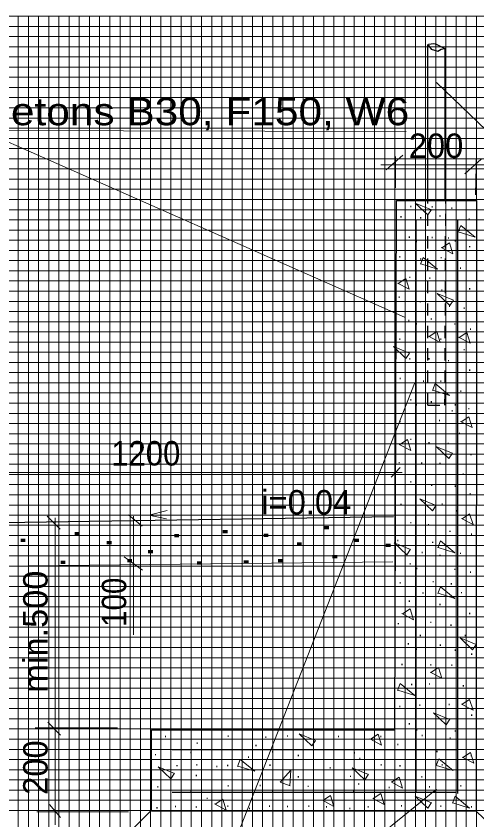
# Model space of a CAD drawing. Extents: x -265.4 to -236, y -5.8 to 40.6.
# Drawn here: x -244.84 to -240.31, y 7.22 to 15.11 of the extents above; entities that cross this region are included whole.
import ezdxf
from ezdxf.enums import TextEntityAlignment as Align

# ---------------------------------------------------------------- set-up
doc = ezdxf.new("R2010")
doc.units = 0
doc.header["$LTSCALE"] = 0.04
doc.linetypes.add('MEDIUM_DASHED', pattern=[4.5, 3, -1.5])
for name, color, linetype, lineweight in [('1', 7, 'Continuous', 13), ('2', 7, 'MEDIUM_DASHED', 13), ('3', 7, 'Continuous', 13), ('4', 7, 'Continuous', 35), ('63', 7, 'Continuous', 13)]:
    doc.layers.add(name, color=color, linetype=linetype, lineweight=lineweight)

msp = doc.modelspace()

# ---------------------------------------------------------------- linework, layer by layer
at = {"layer": '1'}
for p, q in [((-244.816, 15.11), (-244.816, -5.836)), ((-244.716, 15.11), (-244.716, -5.836)), ((-244.516, 15.11), (-244.516, -5.836)), ((-244.416, 15.11), (-244.416, -5.836)), ((-244.316, 15.11), (-244.316, -5.836)), ((-244.216, 15.11), (-244.216, -5.836)), ((-244.016, 15.11), (-244.016, -5.836)), ((-243.916, 15.11), (-243.916, -5.836)), ((-243.816, 15.11), (-243.816, -5.836)), ((-243.716, 15.11), (-243.716, -5.836)), ((-243.516, 15.11), (-243.516, -5.836)), ((-243.416, 15.11), (-243.416, -5.836)), ((-243.316, 15.11), (-243.316, -5.836)), ((-243.216, 15.11), (-243.216, -5.836)), ((-243.016, 15.11), (-243.016, -5.836)), ((-242.916, 15.11), (-242.916, -5.836)), ((-242.816, 15.11), (-242.816, -5.836)), ((-242.716, 15.11), (-242.716, -5.836)), ((-242.516, 15.11), (-242.516, -5.836)), ((-242.416, 15.11), (-242.416, -5.836)), ((-242.316, 15.11), (-242.316, -5.836)), ((-242.216, 15.11), (-242.216, -5.836)), ((-242.016, 15.11), (-242.016, -5.836)), ((-241.916, 15.11), (-241.916, -5.836)), ((-241.816, 15.11), (-241.816, -5.836)), ((-241.716, 15.11), (-241.716, -5.836)), ((-241.516, 15.11), (-241.516, -5.836)), ((-241.416, 15.11), (-241.416, -5.836)), ((-241.316, 15.11), (-241.316, -5.836)), ((-241.216, 15.11), (-241.216, -5.836)), ((-241.016, 15.11), (-241.016, -5.836)), ((-240.916, 15.11), (-240.916, -5.836)), ((-240.816, 15.11), (-240.816, -5.836)), ((-240.716, 15.11), (-240.716, -5.836)), ((-240.516, 15.11), (-240.516, -5.836)), ((-240.416, 15.11), (-240.416, -5.836)), ((-240.316, 15.11), (-240.316, -5.836)), ((-265.117, 15.009), (-236.007, 15.009)), ((-265.117, 14.909), (-236.007, 14.909)), ((-265.117, 14.809), (-236.007, 14.809)), ((-265.117, 14.709), (-236.007, 14.709)), ((-265.117, 14.509), (-236.007, 14.509)), ((-265.117, 14.409), (-236.007, 14.409)), ((-265.117, 14.309), (-236.007, 14.309)), ((-265.117, 14.209), (-236.007, 14.209)), ((-265.117, 14.009), (-236.007, 14.009)), ((-265.117, 13.909), (-236.007, 13.909)), ((-265.117, 13.809), (-236.007, 13.809)), ((-265.107, 13.708), (-235.997, 13.708)), ((-265.117, 13.509), (-236.007, 13.509)), ((-265.117, 13.409), (-236.007, 13.409)), ((-265.117, 13.309), (-236.007, 13.309)), ((-265.117, 13.209), (-236.007, 13.209)), ((-265.117, 13.009), (-236.007, 13.009)), ((-265.117, 12.909), (-236.007, 12.909)), ((-265.117, 12.809), (-236.007, 12.809)), ((-265.117, 12.709), (-236.007, 12.709)), ((-265.117, 12.509), (-236.007, 12.509)), ((-265.117, 12.409), (-236.007, 12.409)), ((-265.117, 12.309), (-236.007, 12.309)), ((-265.117, 12.209), (-236.007, 12.209)), ((-265.117, 12.009), (-236.007, 12.009)), ((-265.117, 11.909), (-236.007, 11.909)), ((-265.117, 11.809), (-236.007, 11.809)), ((-265.117, 11.709), (-236.007, 11.709)), ((-265.117, 11.509), (-236.007, 11.509)), ((-265.117, 11.409), (-236.007, 11.409)), ((-265.117, 11.309), (-236.007, 11.309)), ((-265.117, 11.209), (-236.007, 11.209)), ((-265.117, 11.009), (-236.007, 11.009)), ((-265.117, 10.909), (-236.007, 10.909)), ((-265.117, 10.809), (-236.007, 10.809)), ((-265.117, 10.709), (-236.007, 10.709)), ((-265.117, 10.509), (-236.007, 10.509)), ((-265.117, 10.409), (-236.007, 10.409)), ((-265.117, 10.309), (-236.007, 10.309)), ((-265.117, 10.21), (-236.007, 10.21)), ((-265.117, 10.01), (-236.007, 10.01)), ((-265.117, 9.91), (-236.007, 9.91)), ((-265.117, 9.81), (-236.007, 9.81)), ((-265.117, 9.71), (-236.007, 9.71)), ((-265.117, 9.51), (-236.007, 9.51)), ((-265.117, 9.41), (-236.007, 9.41)), ((-265.117, 9.31), (-236.007, 9.31)), ((-265.117, 9.21), (-236.007, 9.21)), ((-265.117, 9.01), (-236.007, 9.01)), ((-265.117, 8.91), (-236.007, 8.91)), ((-265.117, 8.81), (-236.007, 8.81)), ((-265.117, 8.71), (-236.007, 8.71)), ((-265.117, 8.51), (-236.007, 8.51)), ((-265.117, 8.41), (-236.007, 8.41)), ((-265.117, 8.31), (-236.007, 8.31)), ((-265.117, 8.21), (-236.007, 8.21)), ((-265.117, 8.01), (-236.007, 8.01)), ((-265.117, 7.91), (-236.007, 7.91)), ((-265.117, 7.81), (-236.007, 7.81)), ((-265.117, 7.71), (-236.007, 7.71)), ((-265.117, 7.51), (-236.007, 7.51)), ((-265.117, 7.41), (-236.007, 7.41)), ((-265.117, 7.31), (-236.007, 7.31))]:
    msp.add_line(p, q, dxfattribs=at)
at = {"layer": '2', "linetype": 'Continuous'}
for p, q in [((-244.616, 15.11), (-244.616, -5.836)), ((-243.616, 15.11), (-243.616, -5.836)), ((-242.616, 15.11), (-242.616, -5.836)), ((-241.616, 15.11), (-241.616, -5.836)), ((-240.616, 15.11), (-240.616, -5.836)), ((-265.117, 14.609), (-236.007, 14.609)), ((-265.117, 13.609), (-236.007, 13.609)), ((-265.117, 12.609), (-236.007, 12.609)), ((-265.117, 11.609), (-236.007, 11.609)), ((-265.117, 10.609), (-236.007, 10.609)), ((-265.117, 9.61), (-236.007, 9.61)), ((-265.117, 8.61), (-236.007, 8.61)), ((-265.117, 7.61), (-236.007, 7.61))]:
    msp.add_line(p, q, dxfattribs=at)
at = {"layer": '3'}
for p, q in [((-244.116, 15.11), (-244.116, -5.836)), ((-243.116, 15.11), (-243.116, -5.836)), ((-242.116, 15.11), (-242.116, -5.836)), ((-241.116, 15.11), (-241.116, -5.836)), ((-265.117, 14.109), (-236.007, 14.109)), ((-265.117, 13.109), (-236.007, 13.109)), ((-265.117, 12.109), (-236.007, 12.109)), ((-265.117, 11.109), (-236.007, 11.109)), ((-265.117, 9.11), (-236.007, 9.11)), ((-265.117, 8.11), (-236.007, 8.11))]:
    msp.add_line(p, q, dxfattribs=at)
at = {"layer": '4', "lineweight": 13}
for p, q in [((-265.117, 15.109), (-236.007, 15.109)), ((-265.117, 10.11), (-236.007, 10.11))]:
    msp.add_line(p, q, dxfattribs=at)
at = {"layer": '63', "lineweight": 25}
for p, q in [((-240.623, 13.308), (-240.623, 14.798)), ((-240.91, 13.105), (-240.91, 7.49)), ((-240.502, 13.105), (-240.502, 7.477)), ((-243.303, 7.91), (-240.502, 7.91)), ((-243.303, 7.49), (-240.528, 7.49))]:
    msp.add_line(p, q, dxfattribs=at)
at = {"layer": '63'}
for p, q in [((-241.04, 13.743), (-241.202, 13.6)), ((-240.324, 13.354), (-240.316, 13.775)), ((-241.112, 13.422), (-241.112, 13.731)), ((-240.269, 13.705), (-240.431, 13.562)), ((-241.254, 13.65), (-240.194, 13.65)), ((-241.064, 10.679), (-241.154, 10.583)), ((-247.197, 10.628), (-241.045, 10.628)), ((-244.531, 10.198), (-244.405, 10.072)), ((-244.453, 10.182), (-244.453, 7.17)), ((-243.731, 10.212), (-243.6, 10.1)), ((-243.682, 10.199), (-243.682, 9.033)), ((-242.637, 10.211), (-243.534, 10.211)), ((-243.775, 9.8), (-243.595, 9.669)), ((-241.136, 9.75), (-245.9, 9.7)), ((-244.525, 8.176), (-244.399, 8.05)), ((-243.842, 8.122), (-244.65, 8.122)), ((-243.318, 5.4), (-240.709, 7.52)), ((-244.507, 7.368), (-244.399, 7.242)), ((-243.734, 7.296), (-244.632, 7.296))]:
    msp.add_line(p, q, dxfattribs=at)
at = {"layer": '63', "linetype": 'MEDIUM_DASHED', "lineweight": 25}
msp.add_line((-240.795, 11.289), (-240.795, 13.289), dxfattribs=at)
at = {"layer": '63', "lineweight": 25}
for points in [[(-240.795, 13.289), (-240.792, 14.831), (-240.76, 14.785), (-240.694, 14.765), (-240.662, 14.785), (-240.629, 14.791), (-240.668, 14.811), (-240.708, 14.831), (-240.734, 14.837), (-240.786, 14.831)], [(-241.13, 10.192), (-247.095, 10.1), (-252.481, 6.504)]]:
    msp.add_lwpolyline(points, dxfattribs=at)
at = {"layer": '63'}
for points in [[(-240.707, 14.459), (-239.976, 13.753), (-236.293, 13.753)], [(-241.007, 13.976), (-245.174, 13.988), (-241.022, 12.153)], [(-240.758, 13.209), (-240.917, 13.274), (-240.794, 13.157), (-240.758, 13.211)], [(-240.495, 12.99), (-240.329, 12.94), (-240.471, 13.055), (-240.498, 12.988)], [(-240.655, 12.835), (-240.58, 12.884), (-240.547, 12.777), (-240.661, 12.837)], [(-240.863, 12.676), (-240.697, 12.626), (-240.839, 12.741), (-240.866, 12.674)], [(-241.086, 12.485), (-241.011, 12.534), (-240.978, 12.427), (-241.092, 12.487)], [(-240.542, 12.32), (-240.701, 12.385), (-240.578, 12.268), (-240.542, 12.322)], [(-240.781, 11.964), (-240.706, 12.013), (-240.673, 11.906), (-240.787, 11.966)], [(-240.485, 11.955), (-240.41, 12.004), (-240.377, 11.897), (-240.491, 11.957)], [(-240.973, 11.799), (-241.132, 11.864), (-241.009, 11.747), (-240.973, 11.801)], [(-240.923, 11.501), (-243.318, 5.4), (-236.668, 5.4)], [(-240.746, 11.436), (-240.58, 11.386), (-240.722, 11.501), (-240.749, 11.434)], [(-240.467, 11.127), (-240.392, 11.176), (-240.359, 11.069), (-240.473, 11.129)], [(-241.068, 10.902), (-240.993, 10.951), (-240.96, 10.844), (-241.074, 10.904)], [(-240.551, 10.817), (-240.71, 10.882), (-240.587, 10.765), (-240.551, 10.819)], [(-240.713, 10.305), (-240.872, 10.37), (-240.749, 10.253), (-240.713, 10.307)], [(-243.353, 10.254), (-243.534, 10.211), (-243.359, 10.173)], [(-240.458, 10.175), (-240.383, 10.224), (-240.35, 10.117), (-240.464, 10.177)], [(-240.693, 9.891), (-240.527, 9.841), (-240.669, 9.956), (-240.696, 9.889)], [(-240.964, 9.873), (-241.123, 9.938), (-241, 9.821), (-240.964, 9.875)], [(-240.693, 9.442), (-240.527, 9.392), (-240.669, 9.507), (-240.696, 9.44)], [(-241.042, 9.241), (-240.967, 9.29), (-240.934, 9.183), (-241.048, 9.243)], [(-240.318, 8.939), (-240.477, 9.004), (-240.354, 8.887), (-240.318, 8.941)], [(-240.763, 8.666), (-240.688, 8.715), (-240.655, 8.608), (-240.769, 8.668)], [(-241.088, 8.49), (-240.922, 8.44), (-241.064, 8.555), (-241.091, 8.488)], [(-240.458, 8.352), (-240.383, 8.401), (-240.35, 8.294), (-240.464, 8.354)], [(-240.578, 8.203), (-240.737, 8.268), (-240.614, 8.151), (-240.578, 8.205)], [(-241.898, 7.996), (-242.057, 8.061), (-241.934, 7.944), (-241.898, 7.998)], [(-241.356, 8.01), (-241.281, 8.059), (-241.248, 7.952), (-241.362, 8.012)], [(-240.71, 7.753), (-240.544, 7.703), (-240.686, 7.818), (-240.713, 7.751)], [(-240.449, 7.831), (-240.374, 7.88), (-240.341, 7.773), (-240.455, 7.833)], [(-243.281, 7.673), (-243.44, 7.738), (-243.317, 7.621), (-243.281, 7.675)], [(-242.659, 7.745), (-242.493, 7.695), (-242.635, 7.81), (-242.662, 7.743)], [(-242.145, 7.552), (-242.242, 7.588), (-242.139, 7.707), (-242.148, 7.552)], [(-241.377, 7.664), (-241.536, 7.729), (-241.413, 7.612), (-241.377, 7.666)], [(-241.149, 7.588), (-241.074, 7.637), (-241.041, 7.53), (-241.155, 7.59)], [(-242.882, 7.372), (-242.807, 7.421), (-242.774, 7.314), (-242.888, 7.374)], [(-241.823, 7.408), (-241.748, 7.457), (-241.715, 7.35), (-241.829, 7.41)], [(-241.329, 7.426), (-241.254, 7.475), (-241.221, 7.368), (-241.335, 7.428)], [(-240.758, 7.385), (-240.917, 7.45), (-240.794, 7.333), (-240.758, 7.387)], [(-240.549, 7.384), (-240.383, 7.334), (-240.525, 7.449), (-240.552, 7.382)], [(-240.32, 7.303), (-239.491, 6.515), (-244.313, 6.506), (-243.505, 7.315)]]:
    msp.add_lwpolyline(points, dxfattribs=at)
at = {"layer": '63', "lineweight": 25}
msp.add_lwpolyline([(-241.1, 13.299), (-240.316, 13.299), (-240.32, 7.303), (-243.507, 7.303), (-243.507, 8.102), (-241.116, 8.103)], close=True, dxfattribs=at)
at = {"layer": '63', "linetype": 'MEDIUM_DASHED', "lineweight": 25}
msp.add_lwpolyline([(-240.795, 11.289), (-240.625, 11.289), (-240.617, 13.302)], dxfattribs=at)

# ---------------------------------------------------------------- texts
at = {"layer": '63'}
for s, height, width, p in [('betons B30, F150, W6', 0.2707, 1.15, (-243.0475, 14.038)), ('.', 0.1, 0.85, (-240.9615, 13.233)), ('.', 0.1, 0.85, (-240.7505, 13.229)), ('.', 0.1, 0.85, (-240.5575, 13.215)), ('.', 0.1, 0.85, (-241.0565, 13.13)), ('.', 0.1, 0.85, (-240.8635, 13.121)), ('.', 0.1, 0.85, (-240.6745, 13.139)), ('.', 0.1, 0.85, (-240.3875, 13.108)), ('.', 0.1, 0.85, (-240.9755, 12.932)), ('.', 0.1, 0.85, (-240.4815, 13)), ('.', 0.1, 0.85, (-240.9045, 12.888)), ('.', 0.1, 0.85, (-240.7505, 12.928)), ('.', 0.1, 0.85, (-240.5895, 12.923)), ('.', 0.1, 0.85, (-240.5235, 12.896)), ('.', 0.1, 0.85, (-240.3825, 12.838)), ('.', 0.1, 0.85, (-241.0695, 12.739)), ('.', 0.1, 0.85, (-240.8635, 12.717)), ('.', 0.1, 0.85, (-240.6615, 12.73)), ('.', 0.1, 0.85, (-240.4725, 12.627)), ('.', 0.1, 0.85, (-240.9705, 12.537)), ('.', 0.1, 0.85, (-240.7735, 12.528)), ('.', 0.1, 0.85, (-240.6565, 12.411)), ('.', 0.1, 0.85, (-240.3825, 12.424)), ('.', 0.1, 0.85, (-241.0745, 12.343)), ('.', 0.1, 0.85, (-240.8675, 12.298)), ('.', 0.1, 0.85, (-240.5805, 12.253)), ('.', 0.1, 0.85, (-240.4365, 12.235)), ('.', 0.1, 0.85, (-240.9795, 12.114)), ('.', 0.1, 0.85, (-240.9045, 12.08)), ('.', 0.1, 0.85, (-240.7595, 12.128)), ('.', 0.1, 0.85, (-240.5275, 12.079)), ('.', 0.1, 0.85, (-240.3735, 12.029)), ('.', 0.1, 0.85, (-241.0695, 11.93)), ('.', 0.1, 0.85, (-240.6655, 11.93)), ('.', 0.1, 0.85, (-240.4365, 11.827)), ('.', 0.1, 0.85, (-240.9705, 11.737)), ('.', 0.1, 0.85, (-240.7825, 11.737)), ('.', 0.1, 0.85, (-240.5895, 11.719)), ('.', 0.1, 0.85, (-240.3825, 11.625)), ('.', 0.1, 0.85, (-241.0655, 11.544)), ('.', 0.1, 0.85, (-240.8365, 11.517)), ('.', 0.1, 0.85, (-240.6655, 11.517)), ('.', 0.1, 0.85, (-240.4685, 11.418)), ('.', 0.1, 0.85, (-240.9615, 11.333)), ('.', 0.1, 0.85, (-240.9045, 11.286)), ('.', 0.1, 0.85, (-240.7595, 11.315)), ('.', 0.1, 0.85, (-240.5235, 11.286)), ('.', 0.1, 0.85, (-240.5535, 11.225)), ('.', 0.1, 0.85, (-240.3915, 11.247)), ('.', 0.1, 0.85, (-241.0655, 11.122)), ('.', 0.1, 0.85, (-240.6795, 11.131)), ('.', 0.1, 0.85, (-240.4815, 11.005)), ('1200', 0.24, 0.95, (-243.563, 10.697)), ('.', 0.1, 0.85, (-240.9615, 10.946)), ('.', 0.1, 0.85, (-240.7825, 10.911)), ('.', 0.1, 0.85, (-240.5935, 10.906)), ('.', 0.1, 0.85, (-240.3695, 10.798)), ('.', 0.1, 0.85, (-241.0745, 10.717)), ('.', 0.1, 0.85, (-240.8545, 10.713)), ('.', 0.1, 0.85, (-240.6745, 10.708)), ('.', 0.1, 0.85, (-240.4455, 10.605)), ('.', 0.1, 0.85, (-240.9615, 10.529)), ('.', 0.1, 0.85, (-240.9095, 10.487)), ('.', 0.1, 0.85, (-240.7555, 10.497)), ('.', 0.1, 0.85, (-240.5235, 10.487)), ('.', 0.1, 0.85, (-240.3785, 10.412)), ('.', 0.1, 0.85, (-241.0565, 10.308)), ('.', 0.1, 0.85, (-240.6525, 10.309)), ('.', 0.1, 0.85, (-240.5035, 10.245)), ('.', 0.1, 0.85, (-240.9615, 10.128)), ('.', 0.1, 0.85, (-240.7865, 10.107)), ('.', 0.1, 0.85, (-240.5755, 10.043)), ('.', 0.1, 0.85, (-240.3645, 10.016)), ('.', 0.1, 0.85, (-241.0875, 9.953)), ('.', 0.1, 0.85, (-240.7465, 9.935)), ('.', 0.1, 0.85, (-240.8495, 9.836)), ('.', 0.1, 0.85, (-240.6745, 9.805)), ('.', 0.1, 0.85, (-240.4725, 9.827)), ('.', 0.1, 0.85, (-240.9665, 9.724)), ('.', 0.1, 0.85, (-240.9005, 9.679)), ('.', 0.1, 0.85, (-240.5275, 9.67)), ('.', 0.1, 0.85, (-240.3735, 9.643)), ('.', 0.1, 0.85, (-241.0655, 9.536)), ('.', 0.1, 0.85, (-240.7415, 9.549)), ('.', 0.1, 0.85, (-240.5625, 9.527)), ('.', 0.1, 0.85, (-240.8405, 9.437)), ('.', 0.1, 0.85, (-240.4635, 9.441)), ('.', 0.1, 0.85, (-240.9755, 9.356)), ('.', 0.1, 0.85, (-240.6745, 9.324)), ('.', 0.1, 0.85, (-240.3825, 9.235)), ('.', 0.1, 0.85, (-240.7645, 9.149)), ('.', 0.1, 0.85, (-241.0835, 9.136)), ('.', 0.1, 0.85, (-240.5665, 9.122)), ('.', 0.1, 0.85, (-240.8675, 9.019)), ('.', 0.1, 0.85, (-240.4275, 9.019)), ('.', 0.1, 0.85, (-240.9845, 8.938)), ('.', 0.1, 0.85, (-240.6705, 8.925)), ('.', 0.1, 0.85, (-240.9055, 8.885)), ('.', 0.1, 0.85, (-240.5235, 8.876)), ('.', 0.1, 0.85, (-240.3635, 8.836)), ('.', 0.1, 0.85, (-241.0475, 8.736)), ('.', 0.1, 0.85, (-240.7635, 8.732)), ('.', 0.1, 0.85, (-240.5575, 8.728)), ('.', 0.1, 0.85, (-240.9525, 8.539)), ('.', 0.1, 0.85, (-240.7775, 8.544)), ('.', 0.1, 0.85, (-240.4445, 8.526)), ('.', 0.1, 0.85, (-241.0695, 8.323)), ('.', 0.1, 0.85, (-240.8715, 8.337)), ('.', 0.1, 0.85, (-240.5835, 8.342)), ('.', 0.1, 0.85, (-240.3635, 8.238)), ('.', 0.1, 0.85, (-240.9755, 8.152)), ('.', 0.1, 0.85, (-240.9005, 8.095)), ('.', 0.1, 0.85, (-240.8485, 8.037)), ('.', 0.1, 0.85, (-240.5235, 8.082)), ('.', 0.1, 0.85, (-243.3695, 8.029)), ('.', 0.1, 0.85, (-243.0575, 7.964)), ('.', 0.1, 0.85, (-242.7545, 8.032)), ('.', 0.1, 0.85, (-242.3845, 8.023)), ('.', 0.1, 0.85, (-242.1705, 8.033)), ('.', 0.1, 0.85, (-241.6705, 8.028)), ('.', 0.1, 0.85, (-241.2545, 8.028)), ('.', 0.1, 0.85, (-240.5745, 8.014)), ('.', 0.1, 0.85, (-242.4805, 7.94)), ('.', 0.1, 0.85, (-241.0875, 7.95)), ('.', 0.1, 0.85, (-240.7035, 7.881)), ('.', 0.1, 0.85, (-243.4675, 7.85)), ('.', 0.1, 0.85, (-243.1205, 7.871)), ('.', 0.1, 0.85, (-242.5545, 7.825)), ('.', 0.1, 0.85, (-242.3185, 7.877)), ('.', 0.1, 0.85, (-242.0655, 7.843)), ('.', 0.1, 0.85, (-241.5155, 7.867)), ('.', 0.1, 0.85, (-241.4615, 7.813)), ('.', 0.1, 0.85, (-240.3685, 7.843)), ('.', 0.1, 0.85, (-243.2565, 7.742)), ('.', 0.1, 0.85, (-243.0625, 7.749)), ('.', 0.1, 0.85, (-242.8645, 7.735)), ('.', 0.1, 0.85, (-242.7585, 7.744)), ('.', 0.1, 0.85, (-242.3435, 7.746)), ('.', 0.1, 0.85, (-241.7515, 7.721)), ('.', 0.1, 0.85, (-241.2525, 7.749)), ('.', 0.1, 0.85, (-241.0665, 7.74)), ('.', 0.1, 0.85, (-240.6535, 7.749)), ('.', 0.1, 0.85, (-243.0665, 7.645)), ('.', 0.1, 0.85, (-242.0655, 7.632)), ('.', 0.1, 0.85, (-241.5535, 7.637)), ('.', 0.1, 0.85, (-241.4725, 7.562)), ('.', 0.1, 0.85, (-240.8535, 7.632)), ('.', 0.1, 0.85, (-243.4435, 7.533)), ('.', 0.1, 0.85, (-243.1205, 7.494)), ('.', 0.1, 0.85, (-242.7545, 7.544)), ('.', 0.1, 0.85, (-242.4395, 7.547)), ('.', 0.1, 0.85, (-242.3175, 7.49)), ('.', 0.1, 0.85, (-241.9685, 7.539)), ('.', 0.1, 0.85, (-241.5235, 7.49)), ('.', 0.1, 0.85, (-241.1735, 7.527)), ('.', 0.1, 0.85, (-240.9095, 7.489)), ('.', 0.1, 0.85, (-240.7765, 7.534)), ('.', 0.1, 0.85, (-240.7205, 7.485)), ('.', 0.1, 0.85, (-240.4695, 7.545)), ('.', 0.1, 0.85, (-242.9605, 7.421)), ('.', 0.1, 0.85, (-240.5235, 7.48)), ('.', 0.1, 0.85, (-243.4525, 7.327)), ('.', 0.1, 0.85, (-243.2705, 7.342)), ('.', 0.1, 0.85, (-243.0665, 7.336)), ('.', 0.1, 0.85, (-242.7565, 7.345)), ('.', 0.1, 0.85, (-242.3485, 7.344)), ('.', 0.1, 0.85, (-242.1705, 7.34)), ('.', 0.1, 0.85, (-241.9625, 7.345)), ('.', 0.1, 0.85, (-241.7875, 7.337)), ('.', 0.1, 0.85, (-241.3785, 7.337)), ('.', 0.1, 0.85, (-241.0525, 7.347)), ('.', 0.1, 0.85, (-240.6665, 7.345)), ('.', 0.1, 0.85, (-240.3655, 7.338)), ('.', 0.1, 0.85, (-242.5435, 7.322)), ('.', 0.1, 0.85, (-241.5585, 7.322))]:
    msp.add_text(s, height=height, dxfattribs=dict(at, width=width)).set_placement(p, align=Align.CENTER)
for s, p in [('200', (-240.713, 13.717)), ('i=0.04', (-241.987, 10.216))]:
    msp.add_text(s, height=0.24, dxfattribs=at).set_placement(p, align=Align.CENTER)
for s, height, width, p in [('.', 0.3, 0.85, (-244.216, 10.028)), ('.', 0.3, 0.85, (-243.237, 10.009)), ('.', 0.3, 0.85, (-242.76, 10.047)), ('.', 0.3, 0.85, (-242.359, 10.012)), ('.', 0.3, 0.85, (-241.763, 10.086)), ('.', 0.3, 0.85, (-244.745, 9.963)), ('.', 0.3, 0.85, (-243.899, 9.938)), ('.', 0.3, 0.85, (-241.471, 9.963)), ('.', 0.3, 0.85, (-242.031, 9.925)), ('.', 0.3, 0.85, (-241.16, 9.913)), ('.', 0.3, 0.85, (-243.493, 9.85)), ('.', 0.3, 0.85, (-241.683, 9.801)), ('.', 0.3, 0.85, (-244.353, 9.745)), ('.', 0.3, 0.85, (-243.699, 9.764)), ('.', 0.3, 0.85, (-243.015, 9.739)), ('.', 0.3, 0.85, (-242.554, 9.751)), ('.', 0.3, 0.85, (-242.218, 9.764)), ('min.500', 0.24, 1.05, (-244.527, 9.0655)), ('100', 0.24, 0.9, (-243.755, 9.3545))]:
    msp.add_text(s, height=height, rotation=90, dxfattribs=dict(at, width=width)).set_placement(p, align=Align.CENTER)
msp.add_text('200', height=0.24, rotation=90, dxfattribs=at).set_placement((-244.527, 7.731), align=Align.CENTER)

doc.saveas('drawing.dxf')
